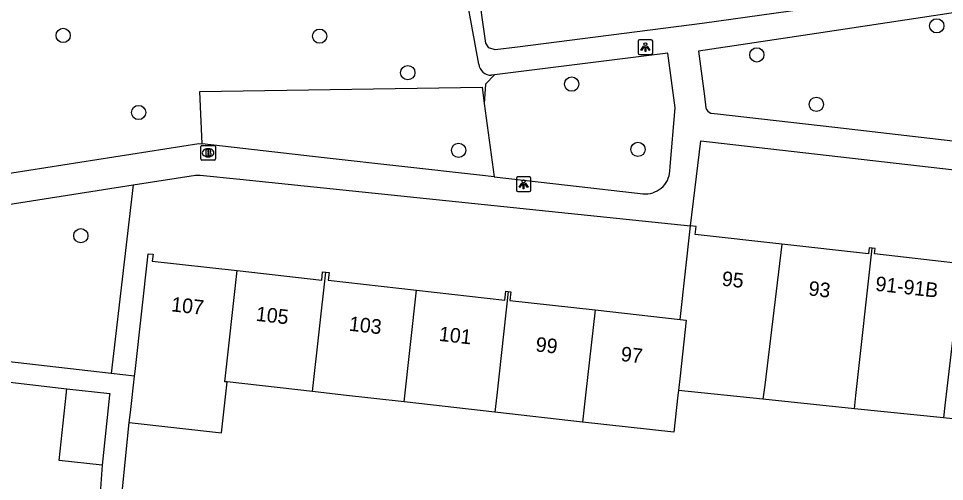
# Model space of a CAD drawing. Extents: x 162026 to 163499, y 387297 to 388169.
# Drawn here: x 162396.7 to 162460.1, y 387494.1 to 387525.8 of the extents above; entities that cross this region are included whole.
import ezdxf

# ---------------------------------------------------------------- set-up
doc = ezdxf.new("R2010")
doc.units = 0
for name, color, linetype in [('IMGEO_Boom', 7, 'Continuous'), ('IMGEO_Brandkraan', 7, 'Continuous'), ('IMGEO_Groenvoorziening', 7, 'Continuous'), ('IMGEO_Lichtpunt', 7, 'Continuous'), ('IMGEO_Pand', 7, 'Continuous'), ('IMGEO_Pand_nummerreeks', 7, 'Continuous'), ('IMGEO_Voetpad_open', 7, 'Continuous')]:
    doc.layers.add(name, color=color, linetype=linetype)

msp = doc.modelspace()

# ---------------------------------------------------------------- linework, layer by layer
at = {"layer": 'IMGEO_Boom'}
for centre in [(162459.617, 387525.304), (162399.745, 387524.643), (162417.321, 387524.595), (162447.285, 387523.312), (162423.363, 387522.092), (162434.597, 387521.31), (162451.365, 387519.921), (162404.917, 387519.365), (162426.846, 387516.774), (162439.14, 387516.836), (162400.957, 387510.919)]:
    msp.add_circle(centre, 0.489, dxfattribs=at)
at = {"layer": 'IMGEO_Brandkraan'}
for p, q in [((162409.177, 387516.178), (162409.177, 387517.03)), ((162409.252, 387517.104), (162410.104, 387517.104)), ((162410.178, 387517.03), (162410.178, 387516.178)), ((162409.688, 387516.324), (162409.663, 387516.324)), ((162409.665, 387516.884), (162409.69, 387516.884)), ((162410.104, 387516.104), (162409.252, 387516.104))]:
    msp.add_line(p, q, dxfattribs=at)
for points in [[(162409.177, 387516.178), (162409.177, 387517.03)], [(162409.252, 387517.104), (162410.104, 387517.104)], [(162410.178, 387517.03), (162410.178, 387516.178)], [(162409.525, 387516.804), (162409.525, 387516.404), (162409.738, 387516.404)], [(162409.756, 387516.804), (162409.525, 387516.804)], [(162409.704, 387516.723), (162409.65, 387516.723), (162409.65, 387516.647)], [(162409.65, 387516.647), (162409.703, 387516.647)], [(162409.712, 387516.571), (162409.65, 387516.571), (162409.65, 387516.49)], [(162409.65, 387516.49), (162409.712, 387516.49)], [(162410.104, 387516.104), (162409.252, 387516.104)]]:
    msp.add_lwpolyline(points, dxfattribs=at)
for centre, radius, start, end in [((162409.254, 387517.028), 0.0765, 91.55205, 178.44795), ((162409.254, 387517.028), 0.0765, 91.55205, 178.44795), ((162410.102, 387517.028), 0.0765, 1.55205, 88.44795), ((162410.102, 387517.028), 0.0765, 1.55205, 88.44795), ((162409.705, 387516.685), 0.0379, 267.82845, 90.93552), ((162409.713, 387516.53), 0.0404, 269.87594, 90.50774), ((162409.744, 387516.655), 0.251, 268.66757, 293.53466), ((162409.76, 387516.659), 0.145, 59.4692, 91.53667), ((162409.785, 387516.706), 0.0922, 285.51372, 58.15012), ((162409.79, 387516.514), 0.105, 301.31148, 78.98903), ((162409.254, 387516.18), 0.0765, 181.55205, 268.44795), ((162409.254, 387516.18), 0.0765, 181.55205, 268.44795), ((162410.102, 387516.18), 0.0765, 271.55205, 358.44795), ((162410.102, 387516.18), 0.0765, 271.55205, 358.44795)]:
    msp.add_arc(centre, radius, start, end, dxfattribs=at)
for centre, major_axis, ratio, start_param, end_param in [((162409.664, 387516.604), (-0.387, 0.002), 0.722429, 4.712389, 7.853982), ((162409.689, 387516.604), (-0.39, 0.002), 0.717154, 1.570796, 4.712389)]:
    msp.add_ellipse(centre, major_axis=major_axis, ratio=ratio, start_param=start_param, end_param=end_param, dxfattribs=at)
at = {"layer": 'IMGEO_Groenvoorziening'}
for points in [[(162429.3, 387521.941), (162428.69, 387521.31), (162428.602, 387519.976)], [(162409.261, 387517.207), (162409.118, 387520.803), (162428.452, 387521.091), (162428.602, 387519.976)], [(162428.602, 387519.976), (162429.278, 387514.953)], [(162404.551, 387514.406), (162403.028, 387501.478)]]:
    msp.add_lwpolyline(points, dxfattribs=at)
at = {"layer": 'IMGEO_Lichtpunt'}
for p, q in [((162439.151, 387524.245), (162439.151, 387523.438)), ((162439.151, 387524.245), (162439.151, 387523.438)), ((162440.053, 387524.34), (162439.245, 387524.34)), ((162440.053, 387524.34), (162439.245, 387524.34)), ((162440.147, 387523.438), (162440.147, 387524.245)), ((162440.147, 387523.438), (162440.147, 387524.245)), ((162439.245, 387523.344), (162440.053, 387523.344)), ((162439.245, 387523.344), (162440.053, 387523.344)), ((162430.804, 387514.851), (162430.804, 387514.044)), ((162430.804, 387514.851), (162430.804, 387514.044)), ((162431.706, 387514.946), (162430.898, 387514.946)), ((162431.706, 387514.946), (162430.898, 387514.946)), ((162431.8, 387514.044), (162431.8, 387514.851)), ((162431.8, 387514.044), (162431.8, 387514.851)), ((162430.898, 387513.95), (162431.706, 387513.95)), ((162430.898, 387513.95), (162431.706, 387513.95))]:
    msp.add_line(p, q, dxfattribs=at)
for points in [[(162439.525, 387523.909), (162439.564, 387523.881), (162439.376, 387523.619), (162439.338, 387523.646), (162439.525, 387523.909)], [(162439.737, 387523.881), (162439.775, 387523.908), (162439.962, 387523.646), (162439.923, 387523.618), (162439.737, 387523.881)], [(162439.627, 387523.861), (162439.674, 387523.861), (162439.674, 387523.539), (162439.627, 387523.539), (162439.627, 387523.861)], [(162431.178, 387514.515), (162431.217, 387514.487), (162431.029, 387514.225), (162430.991, 387514.252), (162431.178, 387514.515)], [(162431.28, 387514.467), (162431.327, 387514.467), (162431.327, 387514.145), (162431.28, 387514.145), (162431.28, 387514.467)], [(162431.39, 387514.487), (162431.428, 387514.514), (162431.615, 387514.252), (162431.576, 387514.224), (162431.39, 387514.487)]]:
    msp.add_lwpolyline(points, dxfattribs=at)
for centre in [(162439.65, 387524.043), (162431.303, 387514.649)]:
    msp.add_circle(centre, 0.0994, dxfattribs=at)
for centre, start, end in [((162439.245, 387524.245), 90, 180), ((162439.245, 387524.245), 90, 180), ((162440.053, 387524.245), 0, 90), ((162440.053, 387524.245), 0, 90), ((162439.245, 387523.438), 180, 270), ((162439.245, 387523.438), 180, 270), ((162440.053, 387523.438), 270, 0), ((162440.053, 387523.438), 270, 360), ((162430.898, 387514.851), 90, 180), ((162430.898, 387514.851), 90, 180), ((162431.706, 387514.851), 0, 90), ((162431.706, 387514.851), 0, 90), ((162430.898, 387514.044), 180, 270), ((162430.898, 387514.044), 180, 270), ((162431.706, 387514.044), 270, 0), ((162431.706, 387514.044), 270, 360)]:
    msp.add_arc(centre, 0.0946, start, end, dxfattribs=at)
at = {"layer": 'IMGEO_Pand'}
for points in [[(162442.029, 387505.182), (162442.75, 387511.59)], [(162449.008, 387510.337), (162443.064, 387511.006), (162443.125, 387511.547), (162442.75, 387511.59)], [(162449.008, 387510.337), (162447.823, 387500.676), (162447.706, 387499.72)], [(162455.198, 387510.062), (162454.995, 387510.085), (162454.948, 387509.669), (162449.008, 387510.337)], [(162453.973, 387499.067), (162454.08, 387499.972), (162455.198, 387510.062)], [(162461.31, 387509.004), (162455.358, 387509.674), (162455.399, 387510.04), (162455.198, 387510.062)], [(162404.636, 387501.297), (162404.671, 387501.607), (162405.58, 387509.689), (162405.907, 387509.653), (162405.857, 387509.188), (162411.66, 387508.535)], [(162461.31, 387509.004), (162460.168, 387499.288), (162460.067, 387498.432)], [(162410.976, 387500.901), (162410.816, 387500.919), (162411.66, 387508.535)], [(162411.66, 387508.535), (162417.465, 387507.882), (162417.53, 387508.454), (162417.752, 387508.429)], [(162416.845, 387500.245), (162417.752, 387508.429)], [(162417.752, 387508.429), (162417.973, 387508.405), (162417.913, 387507.871), (162423.968, 387507.19)], [(162423.119, 387499.532), (162423.968, 387507.19)], [(162423.968, 387507.19), (162430.018, 387506.51), (162430.087, 387507.123), (162430.25, 387507.105)], [(162430.25, 387507.105), (162429.463, 387500.001), (162429.334, 387498.833)], [(162430.25, 387507.105), (162430.415, 387507.086), (162430.361, 387506.494), (162436.195, 387505.838)], [(162436.195, 387505.838), (162435.549, 387500.001), (162435.345, 387498.156)], [(162436.195, 387505.838), (162442.029, 387505.182)], [(162442.029, 387505.182), (162442.451, 387505.135), (162442.023, 387501.328), (162441.91, 387500.323)], [(162404.279, 387498.123), (162404.356, 387498.808), (162404.636, 387501.297)], [(162402.413, 387495.205), (162399.473, 387495.519), (162399.951, 387500), (162399.996, 387500.421)], [(162399.996, 387500.421), (162402.936, 387500.107), (162402.925, 387500), (162402.413, 387495.205)], [(162404.279, 387498.123), (162410.587, 387497.418), (162410.976, 387500.901)], [(162416.845, 387500.245), (162410.976, 387500.901)], [(162466.61, 387500.572), (162466.385, 387498.59), (162466.293, 387497.784), (162460.067, 387498.432)], [(162423.119, 387499.532), (162418.956, 387500), (162416.845, 387500.245)], [(162441.91, 387500.323), (162441.874, 387500), (162441.588, 387497.454), (162435.345, 387498.156)], [(162447.706, 387499.72), (162441.91, 387500.323)], [(162429.334, 387498.833), (162423.119, 387499.532)], [(162453.973, 387499.067), (162447.706, 387499.72)], [(162435.345, 387498.156), (162429.334, 387498.833)], [(162460.067, 387498.432), (162453.973, 387499.067)]]:
    msp.add_lwpolyline(points, dxfattribs=at)
at = {"layer": 'IMGEO_Voetpad_open'}
for points in [[(162503.773, 387534.618), (162466.278, 387528.829), (162451.546, 387526.573), (162443.548, 387525.456), (162430.879, 387523.851), (162429.355, 387523.666), (162428.912, 387523.794), (162428.713, 387524.114), (162428.142, 387528.164)], [(162478.98, 387520.947), (162479.234, 387523.65), (162478.939, 387525.698), (162478.478, 387528.899), (162450.917, 387524.717), (162443.278, 387523.558), (162443.693, 387520.479), (162443.8, 387519.686)], [(162428.224, 387522.683), (162427.322, 387527.677)], [(162441.33, 387515.349), (162441.352, 387515.659), (162441.684, 387519.685), (162441.197, 387523.43), (162429.3, 387521.941)], [(162429.3, 387521.941), (162429.096, 387521.915)], [(162444.135, 387519.323), (162444.599, 387519.266), (162452.625, 387518.351), (162462.301, 387517.247), (162476.823, 387515.738)], [(162385.709, 387513.59), (162409.055, 387517.23), (162409.261, 387517.207)], [(162429.278, 387514.953), (162428.278, 387515.065), (162417.635, 387516.253), (162409.267, 387517.206), (162409.261, 387517.207)], [(162442.75, 387511.59), (162443.453, 387517.421), (162480.419, 387513.193)], [(162404.551, 387514.406), (162408.822, 387515.078), (162409.124, 387515.071), (162411.844, 387514.804), (162442.75, 387511.59)], [(162385.791, 387511.457), (162404.551, 387514.406)], [(162429.278, 387514.953), (162434.303, 387514.393), (162439.484, 387513.798)], [(162403.028, 387501.478), (162384.868, 387503.561)], [(162392.758, 387501.269), (162399.996, 387500.421)], [(162404.636, 387501.297), (162403.028, 387501.478)], [(162403.716, 387492.668), (162404.279, 387498.123)], [(162402.413, 387495.205), (162402.25, 387492.959)]]:
    msp.add_lwpolyline(points, dxfattribs=at)
for centre, radius, start, end in [((162429.09, 387522.787), 0.872, 186.85952, 270.39755), ((162444.266, 387519.78), 0.475, 191.36675, 254.03892), ((162439.66, 387515.462), 1.673, 263.9506, 356.12302)]:
    msp.add_arc(centre, radius, start, end, dxfattribs=at)

# ---------------------------------------------------------------- texts
at = {"layer": 'IMGEO_Pand_nummerreeks'}
for s, rotation, p in [('95', 353.57714, (162444.848, 387507.505)), ('91-91B', 353.57714, (162455.373, 387507.157)), ('93', 353.58287, (162450.791, 387506.836)), ('107', 353.57714, (162407.112, 387505.747)), ('105', 353.58287, (162412.916, 387505.094)), ('103', 353.58297, (162419.294, 387504.416)), ('101', 353.58706, (162425.46, 387503.722)), ('99', 353.57466, (162432.089, 387502.999)), ('97', 353.59433, (162437.925, 387502.343))]:
    msp.add_text(s, height=1, rotation=rotation, dxfattribs=at).set_placement(p)

doc.saveas('drawing.dxf')
